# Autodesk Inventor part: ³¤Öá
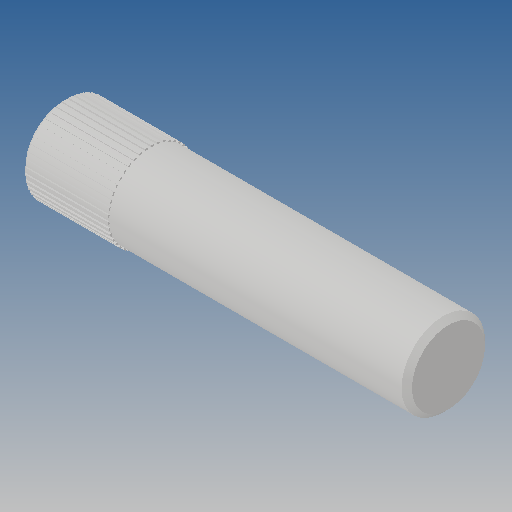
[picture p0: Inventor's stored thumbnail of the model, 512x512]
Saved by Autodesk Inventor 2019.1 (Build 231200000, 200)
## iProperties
Created: 2012-10
Part Number: ³¤Öá
Material: Ogólny
Document SubType Name: Modeling
Designer: CADENGINEERING4
Density: 1 g/cm^3
Appearance: Domyślna
Author: CADENGINEERING4
Revision Number: ÈÎºÎ
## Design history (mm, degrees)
feature "À­Éì2"
node "Bryła1"
